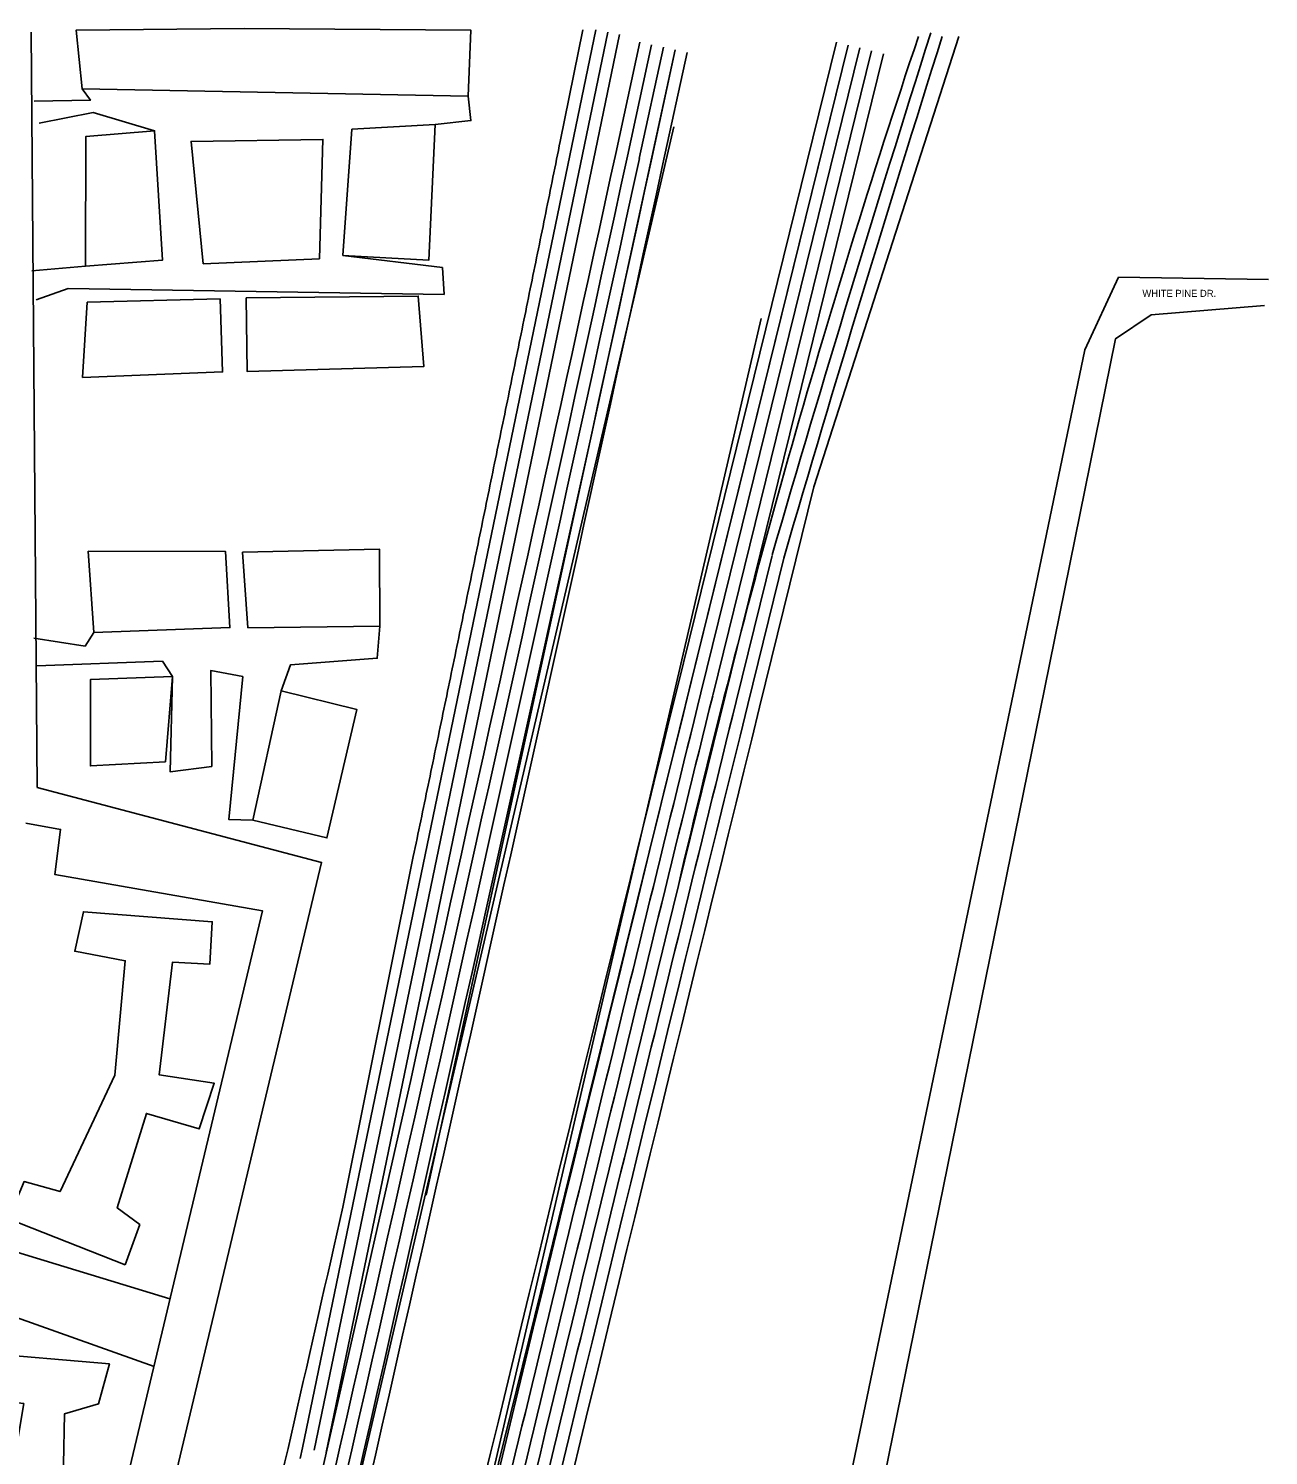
# Model space of a CAD drawing. Extents: x 227157 to 233208, y 434992 to 456232.
# Drawn here: x 229826 to 231057, y 454815 to 456232 of the extents above; entities that cross this region are included whole.
import ezdxf

# ---------------------------------------------------------------- set-up
doc = ezdxf.new("R2010")
doc.units = 0
for name, color, linetype in [('BD_X_Building', 7, 'Continuous'), ('Default', 7, 'Continuous'), ('GE_X_Alignment', 7, 'Continuous'), ('PM_X_Edge_Line', 7, 'Continuous'), ('PM_X_Lane_Line', 7, 'Continuous'), ('PV_X_EOP', 7, 'Continuous'), ('SV_X_Text_Name', 7, 'Continuous')]:
    doc.layers.add(name, color=color, linetype=linetype)

msp = doc.modelspace()

# ---------------------------------------------------------------- linework, layer by layer
at = {"layer": 'BD_X_Building'}
for points in [[(230262.1, 456165.3), (230264.7, 456230.9), (230039.6, 456232.4), (229872.9, 456230.9), (229878.7, 456172.6)], [(229882.2, 455996.4), (229882.3, 456125.1), (229950.7, 456130.8), (229958.4, 456002.2)], [(230137.5, 456007), (230146.7, 456132.3), (230229.2, 456137), (230223, 456002.2)], [(229883.9, 455960.5), (229879.2, 455885.7), (230018.3, 455891.3), (230015.7, 455963.7)], [(230041.5, 455964.7), (230042.6, 455891.7), (230218.1, 455896.7), (230212.5, 455966.5)], [(229884.8, 455713.2), (229890.3, 455632.3), (230025.5, 455637.2), (230021.2, 455712.7)], [(230037.9, 455712.3), (230043.4, 455637.1), (230174.3, 455638.5), (230174.1, 455715)], [(229961.5, 455503.8), (229886.9, 455499.8), (229887, 455585.6), (229968.5, 455588.7)], [(230048.4, 455445.9), (230076.5, 455574.3), (230151.6, 455555.7), (230121.9, 455428.3)], [(229921.6, 455004.3), (229805.6, 455050), (229821.1, 455086.8), (229856.9, 455077), (229911.1, 455192.5), (229921.5, 455306.2), (229871.4, 455315.6), (229880, 455355), (230008, 455345), (230005.6, 455302.9), (229968.6, 455304.9), (229955.4, 455192.9), (230009.9, 455184.6), (229995.1, 455139.2), (229942.6, 455154.5), (229913.6, 455060.7), (229936, 455044.1)]]:
    msp.add_lwpolyline(points, close=True, dxfattribs=at)
msp.add_lwpolyline([(229776.9, 454579.8), (229819.5, 454566), (229837.9, 454602.5), (229811.4, 454611.6), (229845.3, 454714.3), (229898.4, 454706.9), (229906.1, 454744.2), (229859.1, 454755.5), (229861.4, 454856.2), (229895, 454865.9), (229905.8, 454905.9), (229773.6, 454917), (229785.2, 454870.3), (229820.7, 454866.3), (229800.9, 454748.2), (229770.3, 454640.5)], dxfattribs=at)
at = {"layer": 'Default'}
msp.add_open_spline([(230207.6, 455409.8), (230210.1, 455421.6), (230215, 455445.3), (230222.4, 455480.8), (230229.7, 455516.3), (230237.1, 455551.8), (230244.4, 455587.3), (230251.8, 455622.8), (230259.1, 455658.3), (230266.4, 455693.9), (230273.7, 455729.4), (230281, 455764.9), (230288.3, 455800.4), (230295.6, 455836), (230302.9, 455871.5), (230310.1, 455907), (230317.4, 455942.5), (230324.6, 455978.1), (230331.9, 456013.6), (230339.1, 456049.2), (230346.3, 456084.7), (230351.1, 456108.4), (230353.5, 456120.2)], degree=3, dxfattribs=at)
at = {"layer": 'GE_X_Alignment'}
for p, q in [((230141.2, 454193.9), (230639.4, 456216)), ((230220.3, 455073.3), (230467.8, 456211.1)), ((229199.7, 450691.4), (230466.2, 456134.6)), ((229366.4, 450839.2), (230553.2, 455944.3))]:
    msp.add_line(p, q, dxfattribs=at)
for centre, radius, start, end in [((98156.5, 484872.4), 135380, 346.901604, 347.729575), ((384495.2, 417626.5), 158620, 166.15811, 166.912499)]:
    msp.add_arc(centre, radius, start, end, dxfattribs=at)
at = {"layer": 'PM_X_Edge_Line'}
for p, q in [((230097.6, 454822.5), (230389, 456231.1)), ((230121.1, 454817.6), (230412.5, 456226.3)), ((230432.6, 456218.8), (230408.6, 456108.3)), ((230481.6, 455575.3), (230639.4, 456216)), ((230443.8, 456100.6), (230467.8, 456211.1)), ((230470.8, 455381.1), (230674.4, 456207.3)), ((230528.2, 455563.8), (230563.9, 455708.9)), ((230539.8, 455560.9), (230575.6, 455706.1)), ((230095.3, 454811.9), (230097.6, 454822.5))]:
    msp.add_line(p, q, dxfattribs=at)
for centre, radius, start, end in [((252661.3, 449283.2), 23012.8, 162.43533, 163.78474), ((239477.1, 453290.7), 9245.7, 161.50074, 166.93249), ((252661.3, 449283.2), 23000.8, 162.43533, 163.78474), ((98156.5, 484872.4), 135380, 346.901604, 347.729575), ((98156.5, 484872.4), 135344, 347.040271, 347.729575), ((384495.2, 417626.5), 158620, 166.15811, 166.912499), ((384495.2, 417626.5), 158560, 166.15811, 166.912499), ((384495.2, 417626.5), 158572, 166.15811, 166.48524)]:
    msp.add_arc(centre, radius, start, end, dxfattribs=at)
at = {"layer": 'PM_X_Lane_Line'}
for p, q in [((230109.3, 454820.1), (230400.7, 456228.7)), ((230420.3, 456105.7), (230444.3, 456216.2)), ((230456.1, 456213.7), (230432, 456103.2)), ((230493.2, 455572.4), (230651.1, 456213.1)), ((230504.9, 455569.6), (230662.7, 456210.2))]:
    msp.add_line(p, q, dxfattribs=at)
for centre, radius, start, end in [((98156.5, 484872.4), 135356, 346.901604, 347.729575), ((98156.5, 484872.4), 135368, 346.901604, 347.729575), ((384495.2, 417626.5), 158608, 166.15811, 166.48524), ((384495.2, 417626.5), 158596, 166.15811, 166.48524), ((384495.2, 417626.5), 158584, 166.227133, 166.48524)]:
    msp.add_arc(centre, radius, start, end, dxfattribs=at)
at = {"layer": 'PV_X_EOP'}
for p, q in [((229834.2, 455478.4), (229828.3, 456228.7)), ((230353.5, 456120.2), (230375.9, 456231.1)), ((230469.9, 455578.2), (230627.8, 456218.8)), ((230605.4, 455777.1), (230749.2, 456224.4)), ((230455.5, 456098.1), (230479.5, 456208.6)), ((230551.5, 455558.1), (230605.4, 455777.1)), ((230137.6, 455061.5), (230207.6, 455409.8)), ((229966, 454970.5), (229785.5, 455025.2)), ((229950.3, 454903), (229781.7, 454963.2))]:
    msp.add_line(p, q, dxfattribs=at)
for points in [[(229831.2, 456160.3), (229887, 456161.2), (229878.7, 456172.6)], [(230262.1, 456165.3), (230264.8, 456141), (230229.2, 456137)], [(229828.9, 455991.6), (229882.2, 455996.4), (229958.4, 456002.2), (229950.7, 456130.8), (229889.7, 456148.9), (229836, 456138.5)], [(229833.2, 455962.7), (229864.8, 455974), (230238.2, 455968.2), (230236.6, 455994.8), (230137.5, 456007)], [(230508.4, 453661.7), (230517.9, 454121), (230527.3, 454249.6), (230583.9, 454514.9), (230874.3, 455913.3), (230908, 455985.3), (231056.8, 455983.2)], [(231052.7, 455957.2), (230940.3, 455947.9), (230904.9, 455924.1), (230834.4, 455575.9), (230667.4, 454753.2), (230553.6, 454240.1), (230538.5, 454067.2), (230538.9, 453849.4), (230537.6, 453660.4)], [(229830.8, 455626.7), (229881.7, 455618.7), (229890.3, 455632.3)], [(230076.5, 455574.3), (230085.5, 455600.2), (230171.8, 455606.8), (230174.3, 455638.5)], [(229833.8, 455599.3), (229958.5, 455603.8), (229968.5, 455588.7), (229966.2, 455493.8), (230007.4, 455499.3), (230006.5, 455594.5), (230038.2, 455588.6), (230024.3, 455446.6), (230048.4, 455445.9)], [(229790.3, 454055.8), (229955.9, 454729.7), (230116.5, 455404), (229834.2, 455478.4)], [(229822.8, 455443), (229857.4, 455436.7), (229851.6, 455392), (230057.9, 455355.7), (229839.7, 454440.3), (229779.9, 454170.5)]]:
    msp.add_lwpolyline(points, dxfattribs=at)
msp.add_lwpolyline([(229998.8, 455998.5), (229987, 456120.3), (230117.9, 456122.2), (230114.3, 456003.7)], close=True, dxfattribs=at)
for centre, radius, start, end in [((98156.5, 484872.4), 135392, 346.901604, 347.729575), ((384495.2, 417626.5), 158632, 166.15811, 166.912499), ((384495.2, 417626.5), 158548, 166.15811, 166.912499), ((98156.5, 484872.4), 135306, 346.901604, 347.272077)]:
    msp.add_arc(centre, radius, start, end, dxfattribs=at)

# ---------------------------------------------------------------- texts
at = {"layer": 'SV_X_Text_Name'}
msp.add_text('WHITE PINE DR.', height=7, dxfattribs=at).set_placement((230931.6, 455965.8))

doc.saveas('drawing.dxf')
